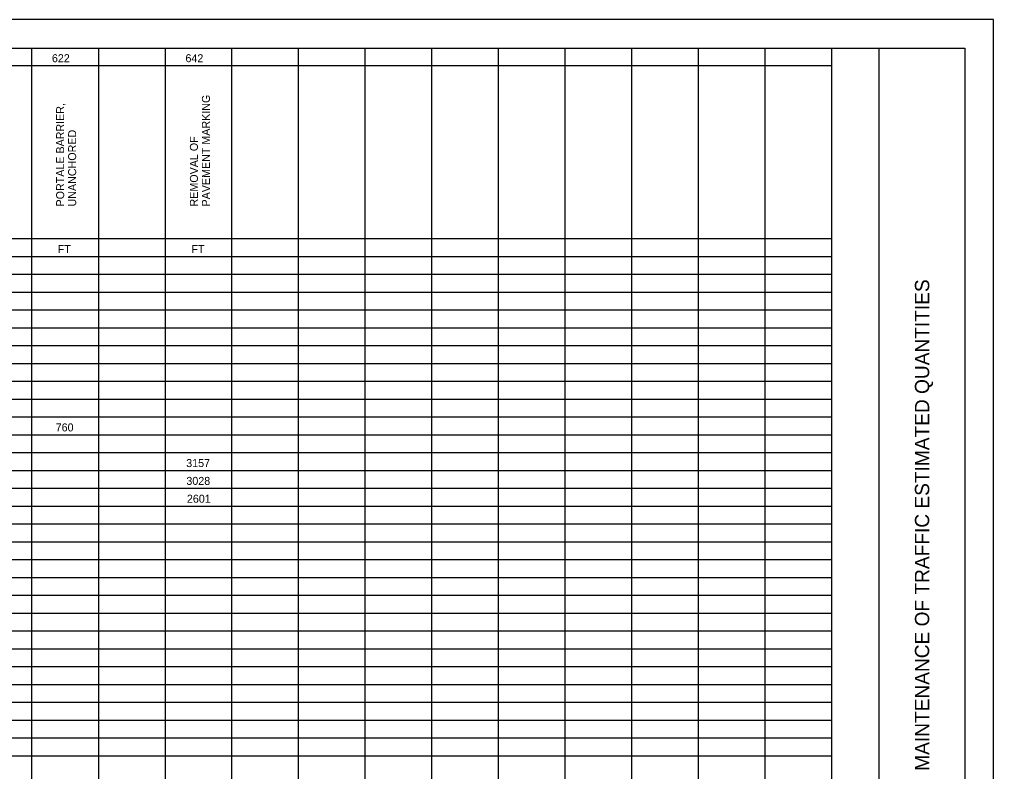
# Model space of a CAD drawing. Extents: x 0 to 34, y 0 to 22.
# Drawn here: x 16.96 to 34, y 8.84 to 22 of the extents above; entities that cross this region are included whole.
import ezdxf

# ---------------------------------------------------------------- set-up
doc = ezdxf.new("R2010")
doc.units = 0
for name, color, linetype in [('Default', 7, 'Continuous'), ('SH_Border', 7, 'Continuous'), ('SH_Cut_Line', 7, 'Continuous'), ('SH_Data', 7, 'Continuous')]:
    doc.layers.add(name, color=color, linetype=linetype)

msp = doc.modelspace()

# ---------------------------------------------------------------- linework, layer by layer
at = {"layer": 'Default'}
for p, q in [((31.167, 18.16), (7.843, 18.16)), ((31.167, 17.536), (1.5, 17.536)), ((31.167, 17.224), (1.5, 17.224)), ((31.167, 16.912), (1.5, 16.912)), ((31.167, 16.6), (1.5, 16.6)), ((31.167, 16.288), (1.5, 16.288)), ((31.167, 15.976), (1.5, 15.976)), ((31.167, 15.664), (1.5, 15.664)), ((31.167, 15.352), (1.5, 15.352)), ((31.167, 15.04), (1.5, 15.04)), ((31.167, 14.728), (1.5, 14.728)), ((31.167, 14.416), (1.5, 14.416)), ((31.167, 14.104), (1.5, 14.104)), ((31.167, 13.792), (1.5, 13.792)), ((31.167, 13.48), (1.5, 13.48)), ((31.167, 13.168), (1.5, 13.168)), ((31.167, 12.856), (1.5, 12.856)), ((31.167, 12.544), (1.5, 12.544)), ((31.167, 12.232), (1.5, 12.232)), ((31.167, 11.92), (1.5, 11.92)), ((31.167, 11.608), (1.5, 11.608)), ((31.167, 11.296), (1.5, 11.296)), ((31.167, 10.984), (1.5, 10.984)), ((31.167, 10.672), (1.5, 10.672)), ((31.167, 10.36), (1.5, 10.36)), ((31.167, 10.048), (1.5, 10.048)), ((31.167, 9.736), (1.5, 9.736)), ((31.167, 9.424), (1.5, 9.424)), ((31.167, 9.112), (1.5, 9.112))]:
    msp.add_line(p, q, dxfattribs=at)
at = {"layer": 'SH_Border'}
msp.add_line((32, 0.5), (32, 21.5), dxfattribs=at)
msp.add_lwpolyline([(1.5, 21.5), (33.5, 21.5), (33.5, 0.5), (1.5, 0.5)], close=True, dxfattribs=at)
at = {"layer": 'SH_Cut_Line'}
msp.add_lwpolyline([(0, 0), (34, 0), (34, 22), (0, 22)], close=True, dxfattribs=at)
at = {"layer": 'SH_Data'}
for p, q in [((17.175, 21.5), (17.175, 0.688)), ((18.345, 21.5), (18.345, 0.688)), ((19.511, 21.5), (19.511, 0.688)), ((20.673, 21.5), (20.673, 0.688)), ((21.839, 21.5), (21.839, 0.688)), ((23.005, 21.5), (23.005, 0.688)), ((23.005, 21.5), (23.005, 0.688)), ((23.005, 21.5), (23.005, 0.688)), ((24.171, 21.5), (24.171, 0.688)), ((24.171, 21.5), (24.171, 0.688)), ((24.171, 21.5), (24.171, 0.688)), ((24.171, 21.5), (24.171, 0.688)), ((25.337, 21.5), (25.337, 0.688)), ((26.503, 21.5), (26.503, 0.688)), ((27.669, 21.5), (27.669, 0.688)), ((28.835, 21.5), (28.835, 0.688)), ((30.001, 21.5), (30.001, 0.688)), ((31.167, 21.5), (31.167, 0.688)), ((31.167, 21.5), (31.167, 0.688)), ((28.835, 21.188), (7.843, 21.188)), ((31.167, 21.188), (28.835, 21.188)), ((31.167, 17.848), (1.5, 17.848))]:
    msp.add_line(p, q, dxfattribs=at)

# ---------------------------------------------------------------- texts
for s, p in [('622', (17.53, 21.252)), ('642', (19.866, 21.252)), ('FT', (17.631, 17.912)), ('FT', (19.971, 17.912)), ('760', (17.596, 14.792)), ('3157', (19.879, 14.168)), ('3028', (19.882, 13.856)), ('2601', (19.891, 13.544))]:
    msp.add_text(s, height=0.14, dxfattribs=at).set_placement(p)
for s, height, p in [('PAVEMENT MARKING', 0.14, (20.294, 18.728)), ('PORTALE BARRIER, ', 0.14, (17.744, 18.728)), ('UNANCHORED', 0.14, (17.954, 18.728)), ('REMOVAL OF ', 0.14, (20.084, 18.728)), ('MAINTENANCE OF TRAFFIC ESTIMATED QUANTITIES', 0.25, (32.875, 8.854))]:
    msp.add_text(s, height=height, rotation=90, dxfattribs=at).set_placement(p)

doc.saveas('drawing.dxf')
